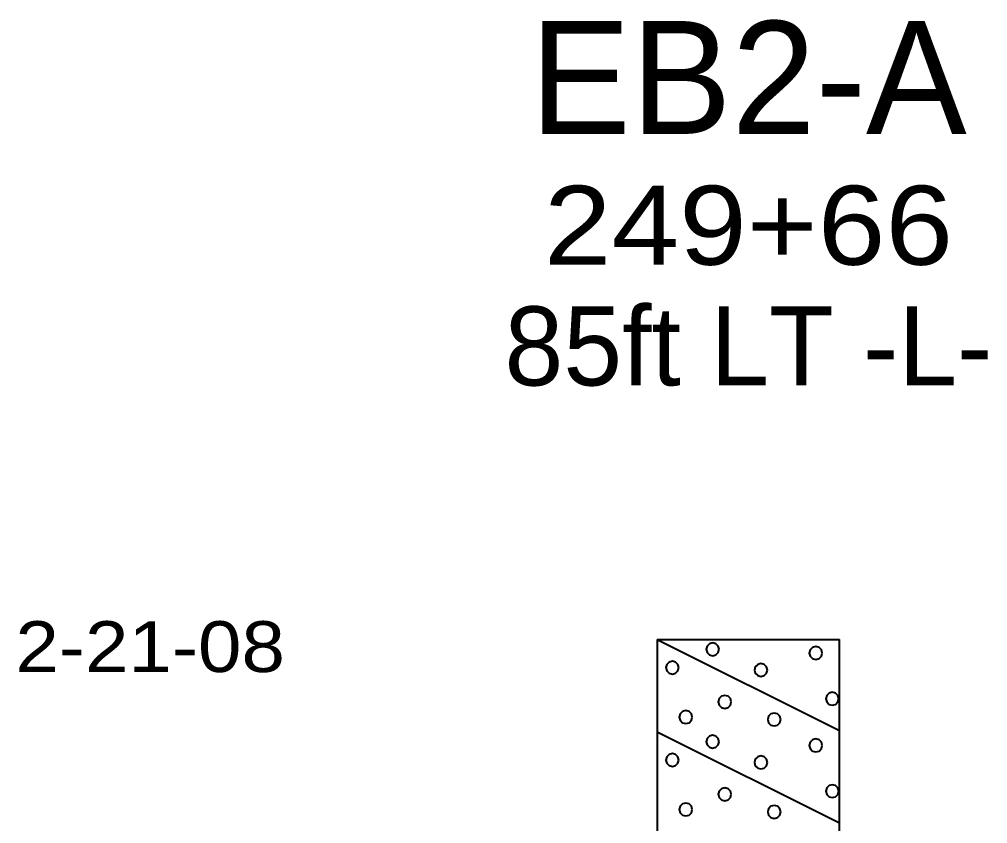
# Model space of a CAD drawing. Extents: x -76 to 974, y -1080 to -735.
# Drawn here: x 6.35 to 19.63, y -770.75 to -759.7 of the extents above; entities that cross this region are included whole.
import ezdxf
from ezdxf.enums import TextEntityAlignment as Align

# ---------------------------------------------------------------- set-up
doc = ezdxf.new("R2010")
doc.units = 0
doc.header["$LTSCALE"] = 0.36
doc.layers.add('27', color=7, linetype='Continuous', lineweight=40)

msp = doc.modelspace()

# ---------------------------------------------------------------- linework, layer by layer
at = {"layer": '27'}
for p, q in [((15.0967, -768.2173), (17.5967, -769.4673)), ((15.0967, -768.2173), (15.0967, -775.2173)), ((15.0967, -768.2173), (17.5967, -768.2173)), ((17.5967, -775.2173), (17.5967, -768.2173)), ((15.0967, -769.4873), (17.5967, -770.7373))]:
    msp.add_line(p, q, dxfattribs=at)
for points in [[(15.9474, -768.3536), (15.9354, -768.3092), (15.9029, -768.2766), (15.8585, -768.2647), (15.814, -768.2766), (15.7815, -768.3092), (15.7696, -768.3536), (15.7815, -768.3981), (15.814, -768.4306), (15.8585, -768.4425), (15.9029, -768.4306), (15.9354, -768.3981)], [(17.3622, -768.4045), (17.3503, -768.3601), (17.3177, -768.3275), (17.2733, -768.3156), (17.2288, -768.3275), (17.1963, -768.3601), (17.1844, -768.4045), (17.1963, -768.449), (17.2288, -768.4815), (17.2733, -768.4934), (17.3177, -768.4815), (17.3503, -768.449)], [(15.3943, -768.6054), (15.3824, -768.5609), (15.3498, -768.5284), (15.3054, -768.5165), (15.2609, -768.5284), (15.2284, -768.5609), (15.2165, -768.6054), (15.2284, -768.6498), (15.2609, -768.6824), (15.3054, -768.6943), (15.3498, -768.6824), (15.3824, -768.6498)], [(16.6096, -768.6384), (16.5977, -768.594), (16.5652, -768.5615), (16.5207, -768.5495), (16.4763, -768.5615), (16.4437, -768.594), (16.4318, -768.6384), (16.4437, -768.6829), (16.4763, -768.7154), (16.5207, -768.7273), (16.5652, -768.7154), (16.5977, -768.6829)], [(17.5885, -769.0325), (17.5766, -768.9881), (17.544, -768.9555), (17.4996, -768.9436), (17.4551, -768.9555), (17.4226, -768.9881), (17.4107, -769.0325), (17.4226, -769.077), (17.4551, -769.1095), (17.4996, -769.1214), (17.544, -769.1095), (17.5766, -769.077)], [(16.1138, -769.0758), (16.1019, -769.0313), (16.0694, -768.9988), (16.0249, -768.9869), (15.9805, -768.9988), (15.9479, -769.0313), (15.936, -769.0758), (15.9479, -769.1202), (15.9805, -769.1528), (16.0249, -769.1647), (16.0694, -769.1528), (16.1019, -769.1202)], [(15.5786, -769.2843), (15.5667, -769.2398), (15.5342, -769.2073), (15.4897, -769.1954), (15.4453, -769.2073), (15.4127, -769.2398), (15.4008, -769.2843), (15.4127, -769.3287), (15.4453, -769.3612), (15.4897, -769.3732), (15.5342, -769.3612), (15.5667, -769.3287)], [(16.7914, -769.3173), (16.7795, -769.2729), (16.7469, -769.2403), (16.7025, -769.2284), (16.658, -769.2403), (16.6255, -769.2729), (16.6136, -769.3173), (16.6255, -769.3618), (16.658, -769.3943), (16.7025, -769.4062), (16.7469, -769.3943), (16.7795, -769.3618)], [(15.9473, -769.6224), (15.9354, -769.578), (15.9028, -769.5454), (15.8584, -769.5335), (15.8139, -769.5454), (15.7814, -769.578), (15.7695, -769.6224), (15.7814, -769.6669), (15.8139, -769.6994), (15.8584, -769.7113), (15.9028, -769.6994), (15.9354, -769.6669)], [(17.3622, -769.6733), (17.3503, -769.6288), (17.3177, -769.5963), (17.2733, -769.5844), (17.2288, -769.5963), (17.1963, -769.6288), (17.1844, -769.6733), (17.1963, -769.7177), (17.2288, -769.7502), (17.2733, -769.7622), (17.3177, -769.7502), (17.3503, -769.7177)], [(15.3943, -769.8741), (15.3824, -769.8297), (15.3498, -769.7971), (15.3054, -769.7852), (15.2609, -769.7971), (15.2284, -769.8297), (15.2165, -769.8741), (15.2284, -769.9186), (15.2609, -769.9511), (15.3054, -769.963), (15.3498, -769.9511), (15.3824, -769.9186)], [(16.6096, -769.9072), (16.5977, -769.8627), (16.5652, -769.8302), (16.5207, -769.8183), (16.4763, -769.8302), (16.4437, -769.8627), (16.4318, -769.9072), (16.4437, -769.9516), (16.4763, -769.9842), (16.5207, -769.9961), (16.5652, -769.9842), (16.5977, -769.9516)], [(16.1138, -770.3445), (16.1019, -770.3), (16.0694, -770.2675), (16.0249, -770.2556), (15.9805, -770.2675), (15.9479, -770.3), (15.936, -770.3445), (15.9479, -770.3889), (15.9805, -770.4215), (16.0249, -770.4334), (16.0694, -770.4215), (16.1019, -770.3889)], [(17.5885, -770.3013), (17.5766, -770.2568), (17.544, -770.2243), (17.4996, -770.2124), (17.4551, -770.2243), (17.4226, -770.2568), (17.4107, -770.3013), (17.4226, -770.3457), (17.4551, -770.3783), (17.4996, -770.3902), (17.544, -770.3783), (17.5766, -770.3457)], [(15.5786, -770.553), (15.5667, -770.5085), (15.5342, -770.476), (15.4897, -770.4641), (15.4453, -770.476), (15.4127, -770.5085), (15.4008, -770.553), (15.4127, -770.5974), (15.4453, -770.63), (15.4897, -770.6419), (15.5342, -770.63), (15.5667, -770.5974)], [(16.7914, -770.586), (16.7795, -770.5416), (16.7469, -770.509), (16.7025, -770.4971), (16.658, -770.509), (16.6255, -770.5416), (16.6136, -770.586), (16.6255, -770.6305), (16.658, -770.663), (16.7025, -770.6749), (16.7469, -770.663), (16.7795, -770.6305)]]:
    msp.add_lwpolyline(points, close=True, dxfattribs=at)

# ---------------------------------------------------------------- texts
for s, height, p in [('EB2-A', 1.55, (16.3484, -761.2778)), ('85ft LT -L-', 1.085, (16.3488, -764.7312))]:
    msp.add_text(s, height=height, dxfattribs=at).set_placement(p, align=Align.CENTER)
at = {"layer": '27', "width": 1.15}
for s, height, p in [('249+66', 1.085, (16.3494, -763.0742)), ('2-21-08', 0.6976, (8.1421, -768.6657))]:
    msp.add_text(s, height=height, dxfattribs=at).set_placement(p, align=Align.CENTER)

doc.saveas('drawing.dxf')
